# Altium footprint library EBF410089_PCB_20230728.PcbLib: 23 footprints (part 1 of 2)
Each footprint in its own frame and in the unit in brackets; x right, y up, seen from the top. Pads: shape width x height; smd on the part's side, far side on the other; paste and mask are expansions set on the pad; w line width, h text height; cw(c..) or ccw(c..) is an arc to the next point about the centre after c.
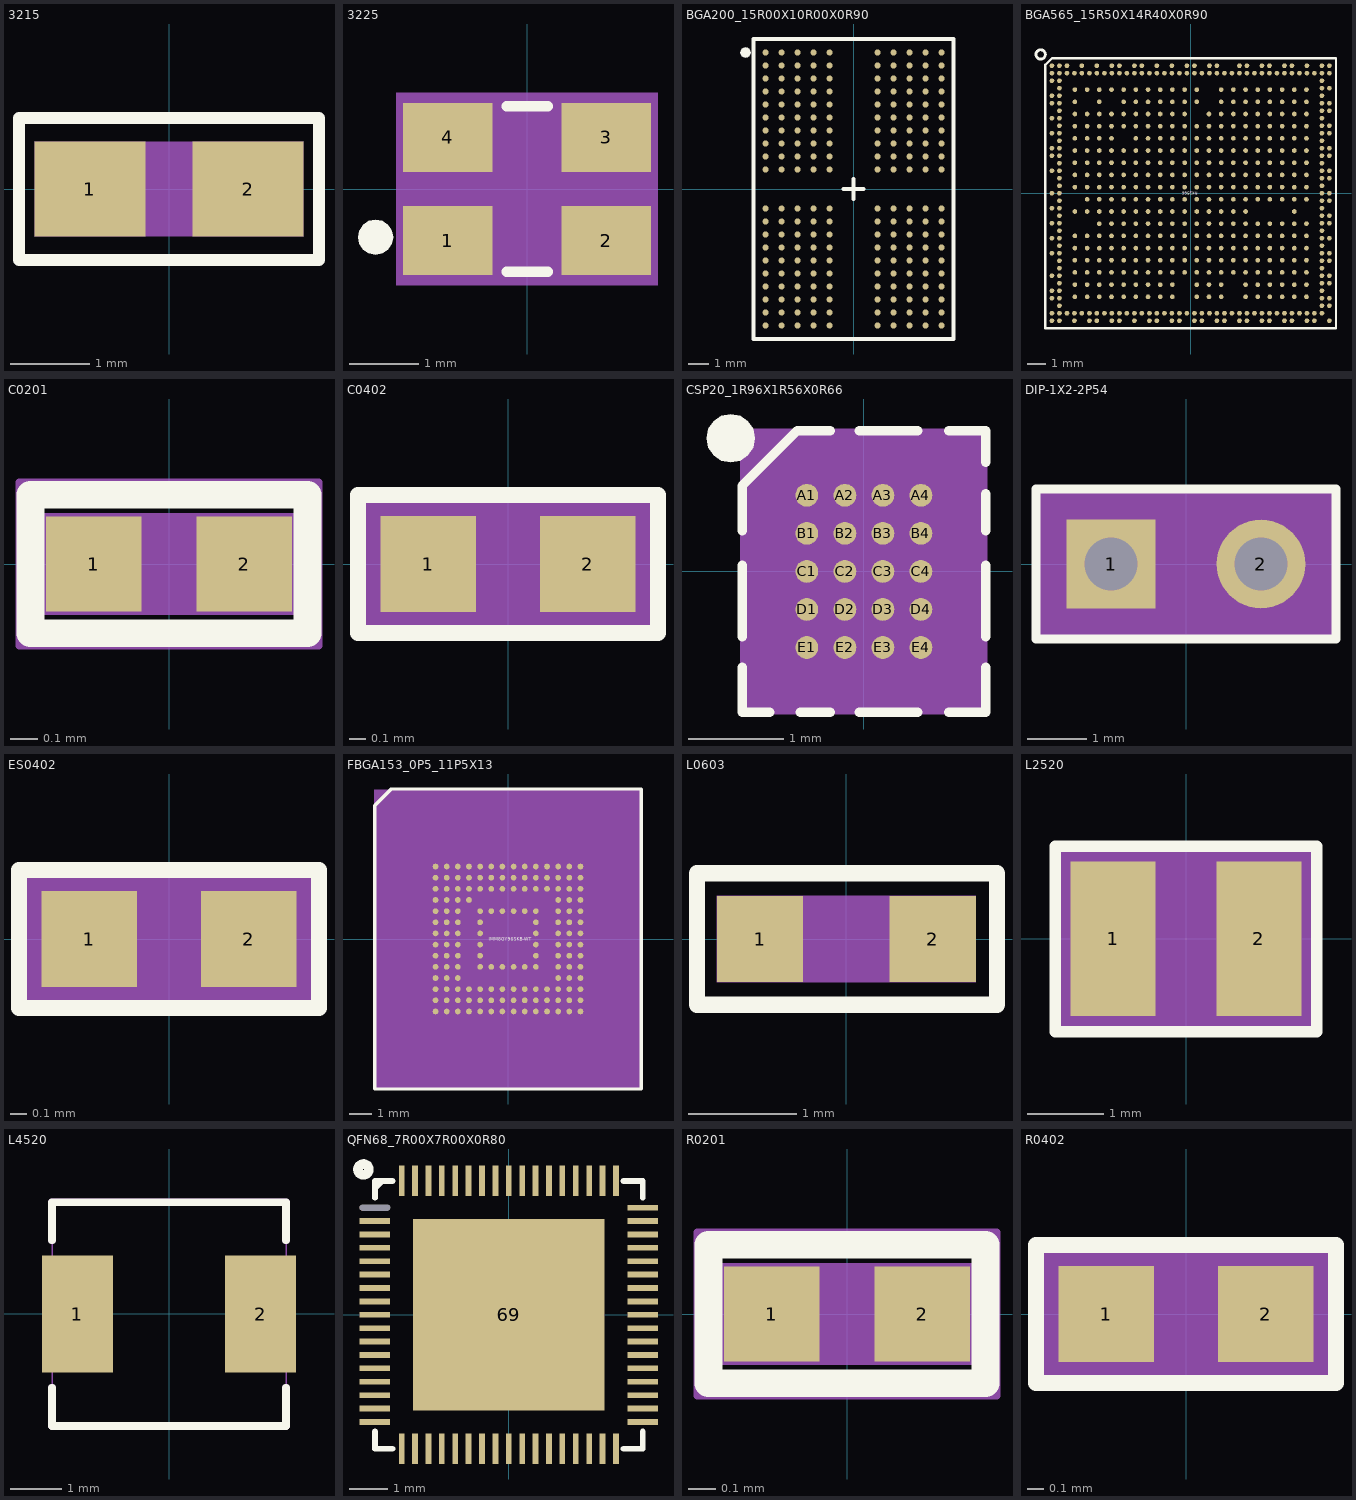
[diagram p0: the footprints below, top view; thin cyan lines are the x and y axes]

## 3215 [mm] "3215"
pads (2):
  rect 1.4x1.2 smd: 1(-1.001,0) 2(1.001,0)
Top Overlay:
  lines w0.15: -1.9,-0.899 -1.9,0.899 1.9,0.899 1.9,-0.899 -1.9,-0.899
Top 3D Body:
  region: -1.699,-0.599 1.699,-0.599 1.699,0.599 -1.699,0.599
Mechanical 12:
  text "1" at -0.848,0 h0.38
  text "2" at 1.153,0 h0.38
3D body: height 3.81, standoff 0, extent -1.699,-0.599 1.699,0.599

## 3225 [mm] "3225"
pads (4):
  rect 1.3x1 smd: 1(-1.15,-0.75) 2(1.15,-0.75) 3(1.15,0.75) 4(-1.15,0.75)
Top Overlay:
  dashed: -2.2,-0.955 -2.102,-0.935 -2.02,-0.88 -1.965,-0.798 -1.945,-0.7 -1.965,-0.602 -1.983,-0.575 -2.02,-0.52 -2.102,-0.465 -2.2,-0.445 -2.298,-0.465 -2.38,-0.52 -2.417,-0.575 -2.435,-0.602 -2.455,-0.7 -2.435,-0.798 -2.38,-0.88 -2.298,-0.935
  lines w0.15: -0.3,-1.2 0.3,-1.2 ; -0.3,1.2 0.3,1.2
Top 3D Body:
  region: -1.9,1.4 -1.9,-1.4 1.9,-1.4 1.9,1.4
Mechanical 12:
  text "2" at 1.15,-0.384 h0.91
  text "1" at -1.15,-0.384 h0.91
Top Assembly:
  lines w0.15: -1.6,-1.25 1.6,-1.25 1.6,1.25 -1.6,1.25 -1.6,-1.25
3D body: height 3.81, standoff 0, extent -1.9,-1.4 1.9,1.4

## BGA200_15R00X10R00X0R90 [mm] "BGA200_15R00X10R00X0R90"
pads (200):
  round 0.3 smd: A1(-4.4,6.825) A2(-3.6,6.825) A3(-2.8,6.825) A4(-2,6.825) A5(-1.2,6.825) A8(1.2,6.825) A9(2,6.825) A10(2.8,6.825) A11(3.6,6.825) A12(4.4,6.825) AA1(-4.4,-6.175) AA2(-3.6,-6.175) AA3(-2.8,-6.175) AA4(-2,-6.175) AA5(-1.2,-6.175) AA8(1.2,-6.175) AA9(2,-6.175) AA10(2.8,-6.175) AA11(3.6,-6.175) AA12(4.4,-6.175) AB1(-4.4,-6.825) AB2(-3.6,-6.825) AB3(-2.8,-6.825) AB4(-2,-6.825) AB5(-1.2,-6.825) AB8(1.2,-6.825) AB9(2,-6.825) AB10(2.8,-6.825) AB11(3.6,-6.825) AB12(4.4,-6.825) B1(-4.4,6.175) B2(-3.6,6.175) B3(-2.8,6.175) B4(-2,6.175) B5(-1.2,6.175) B8(1.2,6.175) B9(2,6.175) B10(2.8,6.175) B11(3.6,6.175) B12(4.4,6.175) C1(-4.4,5.525) C2(-3.6,5.525) C3(-2.8,5.525) C4(-2,5.525) C5(-1.2,5.525) C8(1.2,5.525) C9(2,5.525) C10(2.8,5.525) C11(3.6,5.525) C12(4.4,5.525) D1(-4.4,4.875) D2(-3.6,4.875) D3(-2.8,4.875) D4(-2,4.875) D5(-1.2,4.875) D8(1.2,4.875) D9(2,4.875) D10(2.8,4.875) D11(3.6,4.875) D12(4.4,4.875) E1(-4.4,4.225) E2(-3.6,4.225) E3(-2.8,4.225) E4(-2,4.225) E5(-1.2,4.225) E8(1.2,4.225) E9(2,4.225) E10(2.8,4.225) E11(3.6,4.225) E12(4.4,4.225) F1(-4.4,3.575) F2(-3.6,3.575) F3(-2.8,3.575) F4(-2,3.575) F5(-1.2,3.575) F8(1.2,3.575) F9(2,3.575) F10(2.8,3.575) F11(3.6,3.575) F12(4.4,3.575) G1(-4.4,2.925) G2(-3.6,2.925) G3(-2.8,2.925) G4(-2,2.925) G5(-1.2,2.925) G8(1.2,2.925) G9(2,2.925) G10(2.8,2.925) G11(3.6,2.925) G12(4.4,2.925) H1(-4.4,2.275) H2(-3.6,2.275) H3(-2.8,2.275) H4(-2,2.275) H5(-1.2,2.275) H8(1.2,2.275) H9(2,2.275) H10(2.8,2.275) H11(3.6,2.275) H12(4.4,2.275) J1(-4.4,1.625) J2(-3.6,1.625) J3(-2.8,1.625) J4(-2,1.625) J5(-1.2,1.625) J8(1.2,1.625) J9(2,1.625) J10(2.8,1.625) J11(3.6,1.625) J12(4.4,1.625) K1(-4.4,0.975) K2(-3.6,0.975) K3(-2.8,0.975) K4(-2,0.975) K5(-1.2,0.975) K8(1.2,0.975) K9(2,0.975) K10(2.8,0.975) K11(3.6,0.975) K12(4.4,0.975) N1(-4.4,-0.975) N2(-3.6,-0.975) N3(-2.8,-0.975) N4(-2,-0.975) N5(-1.2,-0.975) N8(1.2,-0.975) N9(2,-0.975) N10(2.8,-0.975) N11(3.6,-0.975) N12(4.4,-0.975) P1(-4.4,-1.625) P2(-3.6,-1.625) P3(-2.8,-1.625) P4(-2,-1.625) P5(-1.2,-1.625) P8(1.2,-1.625) P9(2,-1.625) P10(2.8,-1.625) P11(3.6,-1.625) P12(4.4,-1.625) R1(-4.4,-2.275) R2(-3.6,-2.275) R3(-2.8,-2.275) R4(-2,-2.275) R5(-1.2,-2.275) R8(1.2,-2.275) R9(2,-2.275) R10(2.8,-2.275) R11(3.6,-2.275) R12(4.4,-2.275) T1(-4.4,-2.925) T2(-3.6,-2.925) T3(-2.8,-2.925) T4(-2,-2.925) T5(-1.2,-2.925) T8(1.2,-2.925) T9(2,-2.925) T10(2.8,-2.925) T11(3.6,-2.925) T12(4.4,-2.925) U1(-4.4,-3.575) U2(-3.6,-3.575) U3(-2.8,-3.575) U4(-2,-3.575) U5(-1.2,-3.575) U8(1.2,-3.575) U9(2,-3.575) U10(2.8,-3.575) U11(3.6,-3.575) U12(4.4,-3.575) V1(-4.4,-4.225) V2(-3.6,-4.225) V3(-2.8,-4.225) V4(-2,-4.225) V5(-1.2,-4.225) V8(1.2,-4.225) V9(2,-4.225) V10(2.8,-4.225) V11(3.6,-4.225) V12(4.4,-4.225) W1(-4.4,-4.875) W2(-3.6,-4.875) W3(-2.8,-4.875) W4(-2,-4.875) W5(-1.2,-4.875) W8(1.2,-4.875) W9(2,-4.875) W10(2.8,-4.875) W11(3.6,-4.875) W12(4.4,-4.875) Y1(-4.4,-5.525) Y2(-3.6,-5.525) Y3(-2.8,-5.525) Y4(-2,-5.525) Y5(-1.2,-5.525) Y8(1.2,-5.525) Y9(2,-5.525) Y10(2.8,-5.525) Y11(3.6,-5.525) Y12(4.4,-5.525)
Top Overlay:
  dashed: -5.22,7.005 -5.302,7.06 -5.4,7.08 -5.498,7.06 -5.58,7.005 -5.636,6.923 -5.642,6.89 -5.655,6.825 -5.636,6.727 -5.58,6.645 -5.498,6.589 -5.4,6.57 -5.335,6.583 -5.302,6.589 -5.22,6.645 -5.165,6.727 -5.145,6.825 -5.165,6.923
  lines w0.2: -0.5,0 0,0 ; 0,-0.5 0,0 ; 0,0.5 0,0 ; 0.5,0 0,0 ; -5,-7.5 5,-7.5 5,7.5 -5,7.5 -5,-7.5
Mechanical 12:
  text "J1" at -4.63,1.395 h0.41
  text "F1" at -4.63,3.345 h0.41

## BGA565_15R50X14R40X0R90 [mil] "BGA565_15R50X14R40X0R90"
pads (565):
  round 9.8 smd: 1A1(-243.1,217.5) 1A2(-217.5,217.5) 1A3(-191.9,217.5) 1A4(-166.3,217.5) 1A5(-140.7,217.5) 1A6(-115.2,217.5) 1A7(-89.6,217.5) 1A8(-64,217.5) 1A9(-38.4,217.5) 1A10(-12.8,217.5) 1A11(12.8,217.5) 1A13(64,217.5) 1A14(89.6,217.5) 1A15(115.2,217.5) 1A16(140.7,217.5) 1A17(166.3,217.5) 1A18(191.9,217.5) 1A19(217.5,217.5) 1A20(243.1,217.5) 1B1(-243.1,191.9) 1B3(-191.9,191.9) 1B5(-140.7,191.9) 1B6(-115.2,191.9) 1B7(-89.6,191.9) 1B8(-64,191.9) 1B9(-38.4,191.9) 1B10(-12.8,191.9) 1B11(12.8,191.9) 1B13(64,191.9) 1B14(89.6,191.9) 1B15(115.2,191.9) 1B16(140.7,191.9) 1B17(166.3,191.9) 1B18(191.9,191.9) 1B19(217.5,191.9) 1B20(243.1,191.9) 1C1(-243.1,166.3) 1C2(-217.5,166.3) 1C3(-191.9,166.3) 1C4(-166.3,166.3) 1C5(-140.7,166.3) 1C6(-115.2,166.3) 1C7(-89.6,166.3) 1C8(-64,166.3) 1C9(-38.4,166.3) 1C10(-12.8,166.3) 1C12(38.4,166.3) 1C13(64,166.3) 1C14(89.6,166.3) 1C15(115.2,166.3) 1C16(140.7,166.3) 1C17(166.3,166.3) 1C18(191.9,166.3) 1C19(217.5,166.3) 1C20(243.1,166.3) 1D1(-243.1,140.7) 1D2(-217.5,140.7) 1D3(-191.9,140.7) 1D4(-166.3,140.7) 1D5(-140.7,140.7) 1D6(-115.2,140.7) 1D7(-89.6,140.7) 1D8(-64,140.7) 1D9(-38.4,140.7) 1D10(-12.8,140.7) 1D11(12.8,140.7) 1D12(38.4,140.7) 1D13(64,140.7) 1D14(89.6,140.7) 1D15(115.2,140.7) 1D16(140.7,140.7) 1D17(166.3,140.7) 1D18(191.9,140.7) 1D19(217.5,140.7) 1D20(243.1,140.7) 1E1(-243.1,115.2) 1E2(-217.5,115.2) 1E3(-191.9,115.2) 1E4(-166.3,115.2) 1E6(-115.2,115.2) 1E7(-89.6,115.2) 1E8(-64,115.2) 1E9(-38.4,115.2) 1E10(-12.8,115.2) 1E11(12.8,115.2) 1E12(38.4,115.2) 1E13(64,115.2) 1E14(89.6,115.2) 1E15(115.2,115.2) 1E16(140.7,115.2) 1E17(166.3,115.2) 1E18(191.9,115.2) 1E19(217.5,115.2) 1E20(243.1,115.2) 1F1(-243.1,89.6) 1F2(-217.5,89.6) 1F3(-191.9,89.6) 1F4(-166.3,89.6) 1F5(-140.7,89.6) 1F6(-115.2,89.6) 1F7(-89.6,89.6) 1F8(-64,89.6) 1F9(-38.4,89.6) 1F10(-12.8,89.6) 1F11(12.8,89.6) 1F12(38.4,89.6) 1F13(64,89.6) 1F14(89.6,89.6) 1F15(115.2,89.6) 1F16(140.7,89.6) 1F17(166.3,89.6) 1F18(191.9,89.6) 1F19(217.5,89.6) 1F20(243.1,89.6) 1G1(-243.1,64) 1G2(-217.5,64) 1G3(-191.9,64) 1G4(-166.3,64) 1G5(-140.7,64) 1G6(-115.2,64) 1G7(-89.6,64) 1G8(-64,64) 1G9(-38.4,64) 1G10(-12.8,64) 1G11(12.8,64) 1G12(38.4,64) 1G13(64,64) 1G14(89.6,64) 1G15(115.2,64) 1G16(140.7,64) 1G17(166.3,64) 1G18(191.9,64) 1G19(217.5,64) 1G20(243.1,64) 1H1(-243.1,38.4) 1H2(-217.5,38.4) 1H3(-191.9,38.4) 1H4(-166.3,38.4) 1H5(-140.7,38.4) 1H6(-115.2,38.4) 1H7(-89.6,38.4) 1H8(-64,38.4) 1H9(-38.4,38.4) 1H10(-12.8,38.4) 1H11(12.8,38.4) 1H12(38.4,38.4) 1H13(64,38.4) 1H14(89.6,38.4) 1H15(115.2,38.4) 1H16(140.7,38.4) 1H17(166.3,38.4) 1H18(191.9,38.4) 1H19(217.5,38.4) 1H20(243.1,38.4) 1J1(-243.1,12.8) 1J2(-217.5,12.8) 1J3(-191.9,12.8) 1J4(-166.3,12.8) 1J5(-140.7,12.8) 1J6(-115.2,12.8) 1J7(-89.6,12.8) 1J8(-64,12.8) 1J9(-38.4,12.8) 1J10(-12.8,12.8) 1J11(12.8,12.8) 1J12(38.4,12.8) 1J13(64,12.8) 1J14(89.6,12.8) 1J15(115.2,12.8) 1J16(140.7,12.8) 1J17(166.3,12.8) 1J18(191.9,12.8) 1J19(217.5,12.8) 1J20(243.1,12.8) 1K2(-217.5,-12.8) 1K3(-191.9,-12.8) 1K4(-166.3,-12.8) 1K5(-140.7,-12.8) 1K6(-115.2,-12.8) 1K7(-89.6,-12.8) 1K8(-64,-12.8) 1K9(-38.4,-12.8) 1K10(-12.8,-12.8) 1K11(12.8,-12.8) 1K12(38.4,-12.8) 1K13(64,-12.8) 1K14(89.6,-12.8) 1K15(115.2,-12.8) 1K16(140.7,-12.8) 1K17(166.3,-12.8) 1K18(191.9,-12.8) 1K19(217.5,-12.8) 1K20(243.1,-12.8) 1L1(-243.1,-38.4) 1L2(-217.5,-38.4) 1L3(-191.9,-38.4) 1L4(-166.3,-38.4) 1L5(-140.7,-38.4) 1L6(-115.2,-38.4) 1L7(-89.6,-38.4) 1L8(-64,-38.4) 1L9(-38.4,-38.4) 1L10(-12.8,-38.4) 1L11(12.8,-38.4) 1L12(38.4,-38.4) 1L13(64,-38.4) 1L14(89.6,-38.4) 1L15(115.2,-38.4) 1L19(217.5,-38.4) 1M3(-191.9,-64) 1M4(-166.3,-64) 1M5(-140.7,-64) 1M6(-115.2,-64) 1M7(-89.6,-64) 1M8(-64,-64) 1M9(-38.4,-64) 1M10(-12.8,-64) 1M11(12.8,-64) 1M12(38.4,-64) 1M13(64,-64) 1M14(89.6,-64) 1M15(115.2,-64) 1M16(140.7,-64) 1M17(166.3,-64) 1M18(191.9,-64) 1M19(217.5,-64) 1M20(243.1,-64) 1N1(-243.1,-89.6) 1N2(-217.5,-89.6) 1N3(-191.9,-89.6) 1N4(-166.3,-89.6) 1N5(-140.7,-89.6) 1N6(-115.2,-89.6) 1N7(-89.6,-89.6) 1N8(-64,-89.6) 1N9(-38.4,-89.6) 1N10(-12.8,-89.6) 1N11(12.8,-89.6) 1N12(38.4,-89.6) 1N13(64,-89.6) 1N14(89.6,-89.6) 1N15(115.2,-89.6) 1N16(140.7,-89.6) 1N17(166.3,-89.6) 1N18(191.9,-89.6) 1N19(217.5,-89.6) 1N20(243.1,-89.6) 1P1(-243.1,-115.2) 1P2(-217.5,-115.2) 1P3(-191.9,-115.2) 1P4(-166.3,-115.2) 1P5(-140.7,-115.2) 1P6(-115.2,-115.2) 1P7(-89.6,-115.2) 1P8(-64,-115.2) 1P9(-38.4,-115.2) 1P10(-12.8,-115.2) 1P11(12.8,-115.2) 1P12(38.4,-115.2) 1P13(64,-115.2) 1P14(89.6,-115.2) 1P15(115.2,-115.2) 1P16(140.7,-115.2) 1P17(166.3,-115.2) 1P18(191.9,-115.2) 1P19(217.5,-115.2) 1P20(243.1,-115.2) 1R1(-243.1,-140.7) 1R2(-217.5,-140.7) 1R3(-191.9,-140.7) 1R4(-166.3,-140.7) 1R5(-140.7,-140.7) 1R6(-115.2,-140.7) 1R7(-89.6,-140.7) 1R8(-64,-140.7) 1R9(-38.4,-140.7) 1R10(-12.8,-140.7) 1R11(12.8,-140.7) 1R12(38.4,-140.7) 1R13(64,-140.7) 1R14(89.6,-140.7) 1R15(115.2,-140.7) 1R16(140.7,-140.7) 1R17(166.3,-140.7) 1R18(191.9,-140.7) 1R19(217.5,-140.7) 1R20(243.1,-140.7) 1T1(-243.1,-166.3) 1T2(-217.5,-166.3) 1T3(-191.9,-166.3) 1T4(-166.3,-166.3) 1T5(-140.7,-166.3) 1T6(-115.2,-166.3) 1T7(-89.6,-166.3) 1T8(-64,-166.3) 1T9(-38.4,-166.3) 1T10(-12.8,-166.3) 1T11(12.8,-166.3) 1T12(38.4,-166.3) 1T13(64,-166.3) 1T14(89.6,-166.3) 1T15(115.2,-166.3) 1T16(140.7,-166.3) 1T17(166.3,-166.3) 1T18(191.9,-166.3) 1T19(217.5,-166.3) 1T20(243.1,-166.3) 1U1(-243.1,-191.9) 1U2(-217.5,-191.9) 1U3(-191.9,-191.9) 1U4(-166.3,-191.9) 1U5(-140.7,-191.9) 1U6(-115.2,-191.9) 1U7(-89.6,-191.9) 1U8(-64,-191.9) 1U9(-38.4,-191.9) 1U11(12.8,-191.9) 1U12(38.4,-191.9) 1U13(64,-191.9) 1U15(115.2,-191.9) 1U16(140.7,-191.9) 1U17(166.3,-191.9) 1U18(191.9,-191.9) 1U19(217.5,-191.9) 1U20(243.1,-191.9) 1V1(-243.1,-217.5) 1V2(-217.5,-217.5) 1V3(-191.9,-217.5) 1V4(-166.3,-217.5) 1V5(-140.7,-217.5) 1V6(-115.2,-217.5) 1V7(-89.6,-217.5) 1V8(-64,-217.5) 1V9(-38.4,-217.5) 1V11(12.8,-217.5) 1V12(38.4,-217.5) 1V13(64,-217.5) 1V15(115.2,-217.5) 1V16(140.7,-217.5) 1V17(166.3,-217.5) 1V18(191.9,-217.5) 1V19(217.5,-217.5) 1V20(243.1,-217.5) A1(-291.3,267.7) A2(-275.6,267.7) A3(-259.8,267.7) A5(-228.4,267.7) A7(-196.9,267.7) A9(-165.4,267.7) A10(-149.6,267.7) A12(-118.1,267.7) A13(-102.4,267.7) A15(-70.9,267.7) A17(-39.4,267.7) A19(-7.9,267.7) A20(7.9,267.7) A22(39.4,267.7) A23(55.1,267.7) A26(102.4,267.7) A27(118.1,267.7) A29(149.6,267.7) A30(165.4,267.7) A32(196.9,267.7) A33(212.6,267.7) A35(244.1,267.7) A37(275.6,267.7) A38(291.3,267.7) AA2(-275.6,-47.2) AA37(275.6,-47.2) AA38(291.3,-47.2) AB1(-291.3,-63) AB2(-275.6,-63) AB37(275.6,-63) AB38(291.3,-63) AC2(-275.6,-78.7) AC37(275.6,-78.7) AD1(-291.3,-94.5) AD2(-275.6,-94.5) AD37(275.6,-94.5) AD38(291.3,-94.5) AE2(-275.6,-110.2) AE37(275.6,-110.2) AF1(-291.3,-126) AF2(-275.6,-126) AF37(275.6,-126) AF38(291.3,-126) AG2(-275.6,-141.7) AG37(275.6,-141.7) AG38(291.3,-141.7) AH2(-275.6,-157.5) AH37(275.6,-157.5) AJ1(-291.3,-173.2) AJ2(-275.6,-173.2) AJ37(275.6,-173.2) AJ38(291.3,-173.2) AK2(-275.6,-189) AK37(275.6,-189) AK38(291.3,-189) AL1(-291.3,-204.7) AL2(-275.6,-204.7) AL37(275.6,-204.7) AM1(-291.3,-220.5) AM2(-275.6,-220.5) AM37(275.6,-220.5) AM38(291.3,-220.5) AN2(-275.6,-236.2) AN37(275.6,-236.2) AN38(291.3,-236.2) AP1(-291.3,-252) AP2(-275.6,-252) AP3(-259.8,-252) AP4(-244.1,-252) AP5(-228.4,-252) AP6(-212.6,-252) AP7(-196.9,-252) AP8(-181.1,-252) AP9(-165.4,-252) AP10(-149.6,-252) AP11(-133.9,-252) AP12(-118.1,-252) AP13(-102.4,-252) AP14(-86.6,-252) AP15(-70.9,-252) AP16(-55.1,-252) AP17(-39.4,-252) AP18(-23.6,-252) AP19(-7.9,-252) AP20(7.9,-252) AP21(23.6,-252) AP22(39.4,-252) AP23(55.1,-252) AP24(70.9,-252) AP25(86.6,-252) AP26(102.4,-252) AP27(118.1,-252) AP28(133.9,-252) AP29(149.6,-252) AP30(165.4,-252) AP31(181.1,-252) AP32(196.9,-252) AP33(212.6,-252) AP34(228.4,-252) AP35(244.1,-252) AP36(259.8,-252) AP37(275.6,-252) AR1(-291.3,-267.7) AR2(-275.6,-267.7) AR4(-244.1,-267.7) AR6(-212.6,-267.7) AR7(-196.9,-267.7) AR9(-165.4,-267.7) AR10(-149.6,-267.7) AR12(-118.1,-267.7) AR14(-86.6,-267.7) AR15(-70.9,-267.7) AR17(-39.4,-267.7) AR18(-23.6,-267.7) AR20(7.9,-267.7) AR21(23.6,-267.7) AR23(55.1,-267.7) AR24(70.9,-267.7) AR26(102.4,-267.7) AR27(118.1,-267.7) AR29(149.6,-267.7) AR30(165.4,-267.7) AR32(196.9,-267.7) AR33(212.6,-267.7) AR35(244.1,-267.7) AR36(259.8,-267.7) AR38(291.3,-267.7) B1(-291.3,252) B2(-275.6,252) B3(-259.8,252) B4(-244.1,252) B5(-228.4,252) B6(-212.6,252) B7(-196.9,252) B8(-181.1,252) B9(-165.4,252) B10(-149.6,252) B11(-133.9,252) B12(-118.1,252) B13(-102.4,252) B14(-86.6,252) B15(-70.9,252) B16(-55.1,252) B17(-39.4,252) B18(-23.6,252) B19(-7.9,252) B20(7.9,252) B21(23.6,252) B22(39.4,252) B23(55.1,252) B24(70.9,252) B25(86.6,252) B26(102.4,252) B27(118.1,252) B28(133.9,252) B29(149.6,252) B30(165.4,252) B31(181.1,252) B32(196.9,252) B33(212.6,252) B34(228.4,252) B35(244.1,252) B36(259.8,252) B37(275.6,252) B38(291.3,252) C1(-291.3,236.2) C2(-275.6,236.2) C37(275.6,236.2) D2(-275.6,220.5) D37(275.6,220.5) D38(291.3,220.5) E1(-291.3,204.7) E2(-275.6,204.7) E37(275.6,204.7) F1(-291.3,189) F2(-275.6,189) F37(275.6,189) F38(291.3,189) G2(-275.6,173.2) G37(275.6,173.2) G38(291.3,173.2) H1(-291.3,157.5) H2(-275.6,157.5) H37(275.6,157.5) J2(-275.6,141.7) J37(275.6,141.7) J38(291.3,141.7) K1(-291.3,126) K2(-275.6,126) K37(275.6,126) K38(291.3,126) L2(-275.6,110.2) L37(275.6,110.2) M1(-291.3,94.5) M2(-275.6,94.5) M37(275.6,94.5) M38(291.3,94.5) N1(-291.3,78.7) N2(-275.6,78.7) N37(275.6,78.7) N38(291.3,78.7) P2(-275.6,63) P37(275.6,63) R1(-291.3,47.2) R2(-275.6,47.2) R37(275.6,47.2) R38(291.3,47.2) T2(-275.6,31.5) T37(275.6,31.5) T38(291.3,31.5) U2(-275.6,15.7) U37(275.6,15.7) V1(-291.3,0) V2(-275.6,0) V37(275.6,0) V38(291.3,0) W2(-275.6,-15.7) W37(275.6,-15.7) W38(291.3,-15.7) Y1(-291.3,-31.5) Y2(-275.6,-31.5) Y37(275.6,-31.5)
Top Overlay:
  circle w5.91: c-314.96,291.34 r9.84
  lines w5: -305.1,-283.5 305.1,-283.5 305.1,283.5 -291.3,283.5 -305.1,269.7 -305.1,-283.5
  text "RK3566" at 14.4,3 h6

## C0201 [mm] "C0201"
pads (2):
  rect 0.35x0.35 smd: 1(-0.275,0) 2(0.275,0)
Top Overlay:
  lines w0.102: -0.508,-0.254 -0.508,0.254 0.508,0.254 0.508,-0.254 -0.508,-0.254
Top 3D Body:
  region: -0.475,-0.175 -0.475,0.175 0.475,0.175 0.475,-0.175
Top Assembly:
  lines w0.025: -0.55,-0.3 0.55,-0.3 0.55,0.3 -0.55,0.3 -0.55,-0.3 ; -0.475,-0.175 0.475,-0.175 0.475,0.175 -0.475,0.175 -0.475,-0.175
3D body: height 3.81, standoff 0, extent -0.475,-0.175 0.475,0.175

## C0402 [mm] "C0402"
pads (2):
  rect 0.599x0.599 smd: 1(-0.5,0) 2(0.5,0)
Top Overlay:
  lines w0.102: -0.94,-0.432 -0.94,0.432 0.94,0.432 0.94,-0.432 -0.94,-0.432
Top 3D Body:
  region: 0.94,0.432 0.94,-0.432 -0.94,-0.432 -0.94,0.432
Top Assembly:
  dashed: -0.94,-0.432 -0.94,0.432 0.94,0.432 0.94,-0.432
3D body: height 3.81, standoff 0, extent -0.94,-0.432 0.94,0.432

## CSP20_1R96X1R56X0R66 [mm] "CSP20_1R96X1R56X0R66"
pads (20):
  round 0.24 smd: A1(-0.6,0.8) A2(-0.2,0.8) A3(0.2,0.8) A4(0.6,0.8) B1(-0.6,0.4) B2(-0.2,0.4) B3(0.2,0.4) B4(0.6,0.4) C1(-0.6,0) C2(-0.2,0) C3(0.2,0) C4(0.6,0) D1(-0.6,-0.4) D2(-0.2,-0.4) D3(0.2,-0.4) D4(0.6,-0.4) E1(-0.6,-0.8) E2(-0.2,-0.8) E3(0.2,-0.8) E4(0.6,-0.8)
Top Overlay:
  dashed: -1.4,1.655 -1.498,1.635 -1.58,1.58 -1.635,1.498 -1.655,1.4 -1.635,1.302 -1.617,1.275 -1.58,1.22 -1.498,1.165 -1.4,1.145 -1.302,1.165 -1.22,1.22 -1.183,1.275 -1.165,1.302 -1.145,1.4 -1.165,1.498 -1.22,1.58 -1.302,1.635
  lines w0.1: -1.28,-1.009 -1.28,-1.48 -0.989,-1.48 ; -1.28,-0.685 -1.28,0.062 ; -1.28,0.43 -1.28,0.9 ; -0.671,-1.48 -0.353,-1.48 ; -0.353,1.48 -0.7,1.48 -1.28,0.9 ; -0.048,-1.48 0.569,-1.48 ; -0.048,1.48 0.569,1.48 ; 0.893,-1.48 1.28,-1.48 1.28,-1.009 ; 0.893,1.48 1.28,1.48 1.28,1.146 ; 1.28,-0.685 1.28,0.062 ; 1.28,0.43 1.28,0.816 ; -1.28,0.9 -1.28,0.9
Top 3D Body:
  region: -1.3,1.5 -1.3,-1.5 1.3,-1.5 1.3,1.5
  region: -0.766,1 -0.766,-1 0.8,-1 0.8,1
Mechanical 12:
  text "D1" at -0.6,-0.603 h0.25
  text "D2" at -0.2,-0.603 h0.25
  text "E1" at -0.6,-1.003 h0.25
  text "E2" at -0.2,-1.003 h0.25
  text "A4" at 0.6,0.597 h0.25
  text "B2" at -0.2,0.197 h0.25
  text "B3" at 0.2,0.197 h0.25
  text "B4" at 0.6,0.197 h0.25
  text "C1" at -0.6,-0.203 h0.25
  text "C2" at -0.2,-0.203 h0.25
  text "C3" at 0.2,-0.203 h0.25
  text "C4" at 0.6,-0.203 h0.25
  text "A1" at -0.6,0.597 h0.25
  text "D3" at 0.2,-0.603 h0.25
  text "D4" at 0.6,-0.603 h0.25
  text "E3" at 0.2,-1.003 h0.25
  text "E4" at 0.6,-1.003 h0.25
  text "B1" at -0.6,0.197 h0.25
  text "A3" at 0.2,0.597 h0.25
  text "A2" at -0.2,0.597 h0.25
3D body: height 3.81, standoff 0, extent -1.3,-1.5 1.3,1.5
3D body: height 3.81, standoff 0, extent -0.766,-1 0.8,1

## DIP-1X2-2P54 [mm] "DIP-1X2-2P54"
pads (2):
  rect 1.5x1.5 hole 0.9: 1(-1.27,0)
  round 1.5 hole 0.9: 2(1.27,0)
Top Overlay:
  lines w0.15: -2.54,-1.27 -2.54,1.27 2.54,1.27 2.54,-1.27 -2.54,-1.27
Bottom Overlay:
  lines w0.6: 0,-0.6 0,0.6
Top 3D Body:
  region: -2.54,-1.27 2.54,-1.27 2.54,1.27 -2.54,1.27
Mechanical 12:
  text "2" at 1.27,0.254 h0.64
  text "1" at -1.27,0.254 h0.64
Top Assembly:
  lines w0.025: -2.54,-1.27 -2.54,1.27 2.54,1.27 2.54,-1.27 -2.54,-1.27
3D body: height 3.81, standoff 0, extent -2.54,-1.27 2.54,1.27

## ES0402 [mm] "ES0402"
pads (2):
  rect 0.599x0.599 smd: 1(-0.5,0) 2(0.5,0)
Top Overlay:
  lines w0.102: -0.94,-0.432 -0.94,0.432 0.94,0.432 0.94,-0.432 -0.94,-0.432
Top 3D Body:
  region: 0.94,0.432 0.94,-0.432 -0.94,-0.432 -0.94,0.432
Top Assembly:
  dashed: -0.94,-0.432 -0.94,0.432 0.94,0.432 0.94,-0.432
3D body: height 3.81, standoff 0, extent -0.94,-0.432 0.94,0.432

## FBGA153_0P5_11P5X13 [mil] "FBGA153_0P5_11P5X13"
pads (153):
  round 10 smd: A1(-127.95,127.95) A2(-108.27,127.95) A3(-88.58,127.95) A4(-68.9,127.95) A5(-49.21,127.95) A6(-29.53,127.95) A7(-9.84,127.95) A8(9.84,127.95) A9(29.53,127.95) A10(49.21,127.95) A11(68.9,127.95) A12(88.58,127.95) A13(108.27,127.95) A14(127.95,127.95) B1(-127.95,108.27) B2(-108.27,108.27) B3(-88.58,108.27) B4(-68.9,108.27) B5(-49.21,108.27) B6(-29.53,108.27) B7(-9.84,108.27) B8(9.84,108.27) B9(29.53,108.27) B10(49.21,108.27) B11(68.9,108.27) B12(88.58,108.27) B13(108.27,108.27) B14(127.95,108.27) C1(-127.95,88.58) C2(-108.27,88.58) C3(-88.58,88.58) C4(-68.9,88.58) C5(-49.21,88.58) C6(-29.53,88.58) C7(-9.84,88.58) C8(9.84,88.58) C9(29.53,88.58) C10(49.21,88.58) C11(68.9,88.58) C12(88.58,88.58) C13(108.27,88.58) C14(127.95,88.58) D1(-127.95,68.9) D2(-108.27,68.9) D3(-88.58,68.9) D4(-68.9,68.9) D12(88.58,68.9) D13(108.27,68.9) D14(127.95,68.9) E1(-127.95,49.21) E2(-108.27,49.21) E3(-88.58,49.21) E5(-49.21,49.21) E6(-29.53,49.21) E7(-9.84,49.21) E8(9.84,49.21) E9(29.53,49.21) E10(49.21,49.21) E12(88.58,49.21) E13(108.27,49.21) E14(127.95,49.21) F1(-127.95,29.53) F2(-108.27,29.53) F3(-88.58,29.53) F5(-49.21,29.53) F10(49.21,29.53) F12(88.58,29.53) F13(108.27,29.53) F14(127.95,29.53) G1(-127.95,9.84) G2(-108.27,9.84) G3(-88.58,9.84) G5(-49.21,9.84) G10(49.21,9.84) G12(88.58,9.84) G13(108.27,9.84) G14(127.95,9.84) H1(-127.95,-9.84) H2(-108.27,-9.84) H3(-88.58,-9.84) H5(-49.21,-9.84) H10(49.21,-9.84) H12(88.58,-9.84) H13(108.27,-9.84) H14(127.95,-9.84) J1(-127.95,-29.53) J2(-108.27,-29.53) J3(-88.58,-29.53) J5(-49.21,-29.53) J10(49.21,-29.53) J12(88.58,-29.53) J13(108.27,-29.53) J14(127.95,-29.53) K1(-127.95,-49.21) K2(-108.27,-49.21) K3(-88.58,-49.21) K5(-49.21,-49.21) K6(-29.53,-49.21) K7(-9.84,-49.21) K8(9.84,-49.21) K9(29.53,-49.21) K10(49.21,-49.21) K12(88.58,-49.21) K13(108.27,-49.21) K14(127.95,-49.21) L1(-127.95,-68.9) L2(-108.27,-68.9) L3(-88.58,-68.9) L12(88.58,-68.9) L13(108.27,-68.9) L14(127.95,-68.9) M1(-127.95,-88.58) M2(-108.27,-88.58) M3(-88.58,-88.58) M4(-68.9,-88.58) M5(-49.21,-88.58) M6(-29.53,-88.58) M7(-9.84,-88.58) M8(9.84,-88.58) M9(29.53,-88.58) M10(49.21,-88.58) M11(68.9,-88.58) M12(88.58,-88.58) M13(108.27,-88.58) M14(127.95,-88.58) N1(-127.95,-108.27) N2(-108.27,-108.27) N3(-88.58,-108.27) N4(-68.9,-108.27) N5(-49.21,-108.27) N6(-29.53,-108.27) N7(-9.84,-108.27) N8(9.84,-108.27) N9(29.53,-108.27) N10(49.21,-108.27) N11(68.9,-108.27) N12(88.58,-108.27) N13(108.27,-108.27) N14(127.95,-108.27) P1(-127.95,-127.95) P2(-108.27,-127.95) P3(-88.58,-127.95) P4(-68.9,-127.95) P5(-49.21,-127.95) P6(-29.53,-127.95) P7(-9.84,-127.95) P8(9.84,-127.95) P9(29.53,-127.95) P10(49.21,-127.95) P11(68.9,-127.95) P12(88.58,-127.95) P13(108.27,-127.95) P14(127.95,-127.95)
Top Overlay:
  lines w6: -235.35,-264.87 -235.35,235.77 -206.24,264.87 235.35,264.87 235.35,-264.87 -235.35,-264.87
  text "IMM8GY96SKB-WT" at -33.6,-3 h6
Top 3D Body:
  region: -236.22,-263.78 236.22,-263.78 236.22,263.78 -236.22,263.78
Top Component Center:
  lines w1: -10,0 10,0 ; 0,-10 0,10
Mechanical 12:
  text "A1" at -135.95,127.95 h10
  text "A10" at 37.21,127.95 h10
  text "A11" at 56.9,127.95 h10
  text "A12" at 76.58,127.95 h10
  text "A13" at 96.27,127.95 h10
  text "A14" at 115.95,127.95 h10
  text "A2" at -116.27,127.95 h10
  text "A8" at 1.84,127.95 h10
  text "A9" at 21.53,127.95 h10
  text "B1" at -135.95,108.27 h10
  text "B10" at 37.21,108.27 h10
  text "B11" at 56.9,108.27 h10
  text "B12" at 76.58,108.27 h10
  text "B13" at 96.27,108.27 h10
  text "B14" at 115.95,108.27 h10
  text "B7" at -17.84,108.27 h10
  text "B8" at 1.84,108.27 h10
  text "B9" at 21.53,108.27 h10
  text "C1" at -135.95,88.58 h10
  text "C10" at 37.21,88.58 h10
  text "C11" at 56.9,88.58 h10
  text "C12" at 76.58,88.58 h10
  text "C13" at 96.27,88.58 h10
  text "C14" at 115.95,88.58 h10
  text "C3" at -96.58,88.58 h10
  text "C7" at -17.84,88.58 h10
  text "C8" at 1.84,88.58 h10
  text "C9" at 21.53,88.58 h10
  text "D1" at -135.95,68.9 h10
  text "D12" at 76.58,68.9 h10
  text "D13" at 96.27,68.9 h10
  text "D14" at 115.95,68.9 h10
  text "D2" at -116.27,68.9 h10
  text "D3" at -96.58,68.9 h10
  text "D4" at -76.9,68.9 h10
  text "E1" at -135.95,49.21 h10
  text "E12" at 76.58,49.21 h10
  text "E13" at 96.27,49.21 h10
  text "E14" at 115.95,49.21 h10
  text "E2" at -116.27,49.21 h10
  text "E3" at -96.58,49.21 h10
  text "F1" at -135.95,29.53 h10
  text "F12" at 76.58,29.53 h10
  text "F13" at 96.27,29.53 h10
  text "F14" at 115.95,29.53 h10
  text "F2" at -116.27,29.53 h10
  text "F3" at -96.58,29.53 h10
  text "G1" at -135.95,9.84 h10
  text "G12" at 76.58,9.84 h10
  text "G13" at 96.27,9.84 h10
  text "G14" at 115.95,9.84 h10
  text "G2" at -116.27,9.84 h10
  text "H1" at -135.95,-9.84 h10
  text "H12" at 76.58,-9.84 h10
  text "H13" at 96.27,-9.84 h10
  text "H14" at 115.95,-9.84 h10
  text "H2" at -116.27,-9.84 h10
  text "H3" at -96.58,-9.84 h10
  text "J1" at -135.95,-29.53 h10
  text "J12" at 76.58,-29.53 h10
  text "J13" at 96.27,-29.53 h10
  text "J14" at 115.95,-29.53 h10
  text "J2" at -116.27,-29.53 h10
  text "J3" at -96.58,-29.53 h10
  text "K1" at -135.95,-49.21 h10
  text "K12" at 76.58,-49.21 h10
  text "K13" at 96.27,-49.21 h10
  text "K14" at 115.95,-49.21 h10
  text "K2" at -116.27,-49.21 h10
  text "K3" at -96.58,-49.21 h10
  text "L1" at -135.95,-68.9 h10
  text "L12" at 76.58,-68.9 h10
  text "L13" at 96.27,-68.9 h10
  text "L14" at 115.95,-68.9 h10
  text "L2" at -116.27,-68.9 h10
  text "L3" at -96.58,-68.9 h10
  text "M1" at -135.95,-88.58 h10
  text "M10" at 37.21,-88.58 h10
  text "M11" at 56.9,-88.58 h10
  text "M12" at 76.58,-88.58 h10
  text "M13" at 96.27,-88.58 h10
  text "M14" at 115.95,-88.58 h10
  text "M2" at -116.27,-88.58 h10
  text "M3" at -96.58,-88.58 h10
  text "M7" at -17.84,-88.58 h10
  text "M8" at 1.84,-88.58 h10
  text "M9" at 21.53,-88.58 h10
  text "N1" at -135.95,-108.27 h10
  text "N10" at 37.21,-108.27 h10
  text "N11" at 56.9,-108.27 h10
  text "N12" at 76.58,-108.27 h10
  text "N13" at 96.27,-108.27 h10
  text "N14" at 115.95,-108.27 h10
  text "N3" at -96.58,-108.27 h10
  text "N6" at -37.53,-108.27 h10
  text "N7" at -17.84,-108.27 h10
  text "N8" at 1.84,-108.27 h10
  text "N9" at 21.53,-108.27 h10
  text "P1" at -135.95,-127.95 h10
  text "P11" at 56.9,-127.95 h10
  text "P12" at 76.58,-127.95 h10
  text "P13" at 96.27,-127.95 h10
  text "P14" at 115.95,-127.95 h10
  text "P2" at -116.27,-127.95 h10
  text "P8" at 1.84,-127.95 h10
  text "P9" at 21.53,-127.95 h10
  text "G3" at -96.58,9.84 h10
  text "K10" at 37.21,-49.21 h10
  text "K6" at -37.53,-49.21 h10
  text "K7" at -17.84,-49.21 h10
  text "P10" at 37.21,-127.95 h10
  text "P7" at -17.84,-127.95 h10
  text "A7" at -17.84,127.95 h10
  text "C5" at -57.21,88.58 h10
  text "E10" at 37.21,49.21 h10
  text "E5" at -57.21,49.21 h10
  text "E8" at 1.84,49.21 h10
  text "E9" at 21.53,49.21 h10
  text "F10" at 37.21,29.53 h10
  text "G10" at 37.21,9.84 h10
  text "C6" at -37.53,88.58 h10
  text "M4" at -76.9,-88.58 h10
  text "N4" at -76.9,-108.27 h10
  text "P3" at -96.58,-127.95 h10
  text "P5" at -57.21,-127.95 h10
  text "B4" at -76.9,108.27 h10
  text "B2" at -116.27,108.27 h10
  text "M6" at -37.53,-88.58 h10
  text "A5" at -57.21,127.95 h10
  text "B5" at -57.21,108.27 h10
  text "C2" at -116.27,88.58 h10
  text "A4" at -76.9,127.95 h10
  text "B6" at -37.53,108.27 h10
  text "M5" at -57.21,-88.58 h10
  text "A3" at -96.58,127.95 h10
  text "B3" at -96.58,108.27 h10
  text "E6" at -37.53,49.21 h10
  text "F5" at -57.21,29.53 h10
  text "J10" at 37.21,-29.53 h10
  text "K9" at 21.53,-49.21 h10
  text "A6" at -37.53,127.95 h10
  text "C4" at -76.9,88.58 h10
  text "E7" at -17.84,49.21 h10
  text "G5" at -57.21,9.84 h10
  text "H10" at 37.21,-9.84 h10
  text "J5" at -57.21,-29.53 h10
  text "K8" at 1.84,-49.21 h10
  text "N2" at -116.27,-108.27 h10
  text "N5" at -57.21,-108.27 h10
  text "P4" at -76.9,-127.95 h10
  text "P6" at -37.53,-127.95 h10
  text "K5" at -57.21,-49.21 h10
  text "H5" at -57.21,-9.84 h10
Top Assembly:
  circle w6: c-188.98,220.47 r26.41
  lines w6: -228.35,-257.87 -228.35,232.87 -203.35,257.87 228.35,257.87 228.35,-257.87 -228.35,-257.87
3D body: height 150, standoff 0, extent -236.22,-263.78 236.22,263.78

## L0603 [mil] "L0603"
pads (2):
  rect 31.5x31.5 smd: 1(-31.5,0) 2(31.5,0)
Top Overlay:
  lines w6: -54.5,-24 -54.5,24 55,24 55,-24 -54.5,-24
Top 3D Body:
  region: -47.24,-15.75 47.24,-15.75 47.24,15.75 -47.24,15.75
3D body: height 150, standoff 0, extent -47.24,-15.75 47.24,15.75

## L2520 [mil] "L2520"
pads (2):
  rect 44x80 smd: 1(-37.75,0) 2(37.75,0)
Top Overlay:
  lines w6: -67.68,-48.15 -67.67,-48.15 67.67,-48.15 67.67,47.92 -67.68,47.92 -67.68,-48.15
Top 3D Body:
  region: -65,-45 65,-45 65,45 -65,45
Mechanical 12:
  text "2" at 37.75,4.72 h11.81
  text "1" at -37.75,4.72 h11.81
3D body: height 150, standoff 0, extent -65,-45 65,45

## L4520 [mm] "L4520"
pads (2):
  rect 1.4x2.3 smd: 1(-1.803,-0.003) 2(1.798,-0.003)
Top Overlay:
  lines w0.15: -2.303,-1.453 -2.303,-2.203 2.297,-2.203 2.297,-1.453 ; -2.303,1.447 -2.303,2.197 2.297,2.197 2.297,1.447
Top 3D Body:
  lines w0.025: -2.303,-2.203 2.302,-2.203 2.302,2.202 -2.303,2.202 -2.303,-2.203
Mechanical 12:
  text "2" at 1.544,-0.003 h0.64
  text "1" at -2.057,-0.003 h0.64
Top Assembly:
  lines w0.15: -2.303,-1.453 -2.303,-2.203 2.297,-2.203 2.297,-1.453 ; -2.303,1.447 -2.303,2.197 2.297,2.197 2.297,1.447

## QFN68_7R00X7R00X0R80 [mil] "QFN68_7R00X7R00X0R80"
pads (69):
  oval 31.5x5.9 smd: 1(-137.8,110.24)
  rect 31.5x5.9 smd: 2(-137.8,96.46) 3(-137.8,82.68) 4(-137.8,68.9) 5(-137.8,55.12) 6(-137.8,41.34) 7(-137.8,27.56) 8(-137.8,13.78) 9(-137.8,0) 10(-137.8,-13.78) 11(-137.8,-27.56) 12(-137.8,-41.34) 13(-137.8,-55.12) 14(-137.8,-68.9) 15(-137.8,-82.68) 16(-137.8,-96.46) 17(-137.8,-110.24) 35(137.8,-110.24) 36(137.8,-96.46) 37(137.8,-82.68) 38(137.8,-68.9) 39(137.8,-55.12) 40(137.8,-41.34) 41(137.8,-27.56) 42(137.8,-13.78) 43(137.8,0) 44(137.8,13.78) 45(137.8,27.56) 46(137.8,41.34) 47(137.8,55.12) 48(137.8,68.9) 49(137.8,82.68) 50(137.8,96.46) 51(137.8,110.24)
  rect 5.9x31.5 smd: 18(-110.24,-137.8) 19(-96.46,-137.8) 20(-82.68,-137.8) 21(-68.9,-137.8) 22(-55.12,-137.8) 23(-41.34,-137.8) 24(-27.56,-137.8) 25(-13.78,-137.8) 26(0,-137.8) 27(13.78,-137.8) 28(27.56,-137.8) 29(41.34,-137.8) 30(55.12,-137.8) 31(68.9,-137.8) 32(82.68,-137.8) 33(96.46,-137.8) 34(110.24,-137.8) 52(110.24,137.8) 53(96.46,137.8) 54(82.68,137.8) 55(68.9,137.8) 56(55.12,137.8) 57(41.34,137.8) 58(27.56,137.8) 59(13.78,137.8) 60(0,137.8) 61(-13.78,137.8) 62(-27.56,137.8) 63(-41.34,137.8) 64(-55.12,137.8) 65(-68.9,137.8) 66(-82.68,137.8) 67(-96.46,137.8) 68(-110.24,137.8)
  rect 196.85x196.85 smd: 69(0,0)
Top Overlay:
  circle w9.84: c-149.61,149.61 r5.57
  lines w5.91: -137.8,-120.08 -137.8,-137.8 -119.69,-137.8 ; -137.8,120.47 -137.8,137.8 -119.69,137.8 ; -137.8,129.92 -129.92,137.8 ; 118.11,-137.8 137.8,-137.8 137.8,-120.08 ; 118.11,137.8 137.8,137.8 137.8,120.47
  text "RK809-5" at 0,-13.8 h6
Mechanical 12:
  text "9" at -137.8,-10 h25
  text "6" at -137.8,31.34 h25
  text "69" at 0,-20 h25

## R0201 [mm] "R0201"
pads (2):
  rect 0.35x0.35 smd: 1(-0.275,0) 2(0.275,0)
Top Overlay:
  lines w0.102: -0.508,-0.254 -0.508,0.254 0.508,0.254 0.508,-0.254 -0.508,-0.254
Top 3D Body:
  region: -0.475,-0.175 0.475,-0.175 0.475,0.175 -0.475,0.175
Top Assembly:
  lines w0.025: -0.55,-0.3 0.55,-0.3 0.55,0.3 -0.55,0.3 -0.55,-0.3 ; -0.475,-0.175 -0.475,0.175 0.475,0.175 0.475,-0.175 -0.475,-0.175
3D body: height 3.81, standoff 0, extent -0.475,-0.175 0.475,0.175

## R0402 [mm] "R0402"
pads (2):
  rect 0.599x0.599 smd: 1(-0.5,0) 2(0.5,0)
Top Overlay:
  lines w0.102: -0.94,-0.432 -0.94,0.432 0.94,0.432 0.94,-0.432 -0.94,-0.432
Top 3D Body:
  region: 0.94,0.432 0.94,-0.432 -0.94,-0.432 -0.94,0.432
Top Assembly:
  dashed: -0.94,-0.432 -0.94,0.432 0.94,0.432 0.94,-0.432
3D body: height 3.81, standoff 0, extent -0.94,-0.432 0.94,0.432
